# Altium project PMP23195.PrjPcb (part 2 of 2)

## Sheet SystemAUX_ZVSFlyback.SchDoc
size 431 x 279 mm; Date: Not shown in title block; ApprovedBy: Not shown in title block; CheckedBy: Not shown in title block; Author: Not shown in title block; CompanyName: Not shown in title block; Engineer: Not shown in title block; Organization: Not shown in title block; Address1: Not shown in title block; Address2: Not shown in title block; Address3: Not shown in title block; Address4: Not shown in title block; DocumentNumber: 1; Revision: Use project parameter SCH_Rev; SheetNumber: 4; SheetTotal: 4; PageSetup: Record=PageOptions¦CenterHorizontal=True¦CenterVertical=True¦PrintScale=1.00¦XCorrection=1.00¦YCorrection=1.00¦PrintKind=0¦BorderSize=5000000¦LeftOffset=0¦BottomOffset=0¦Orientation=2¦PaperLength=1000¦PaperWidth=1000¦Scale=100¦PaperSource=15¦PrintQuality=600¦MediaType=1¦DitherType=10¦PaperKind=Letter¦PrintScaleMode=1
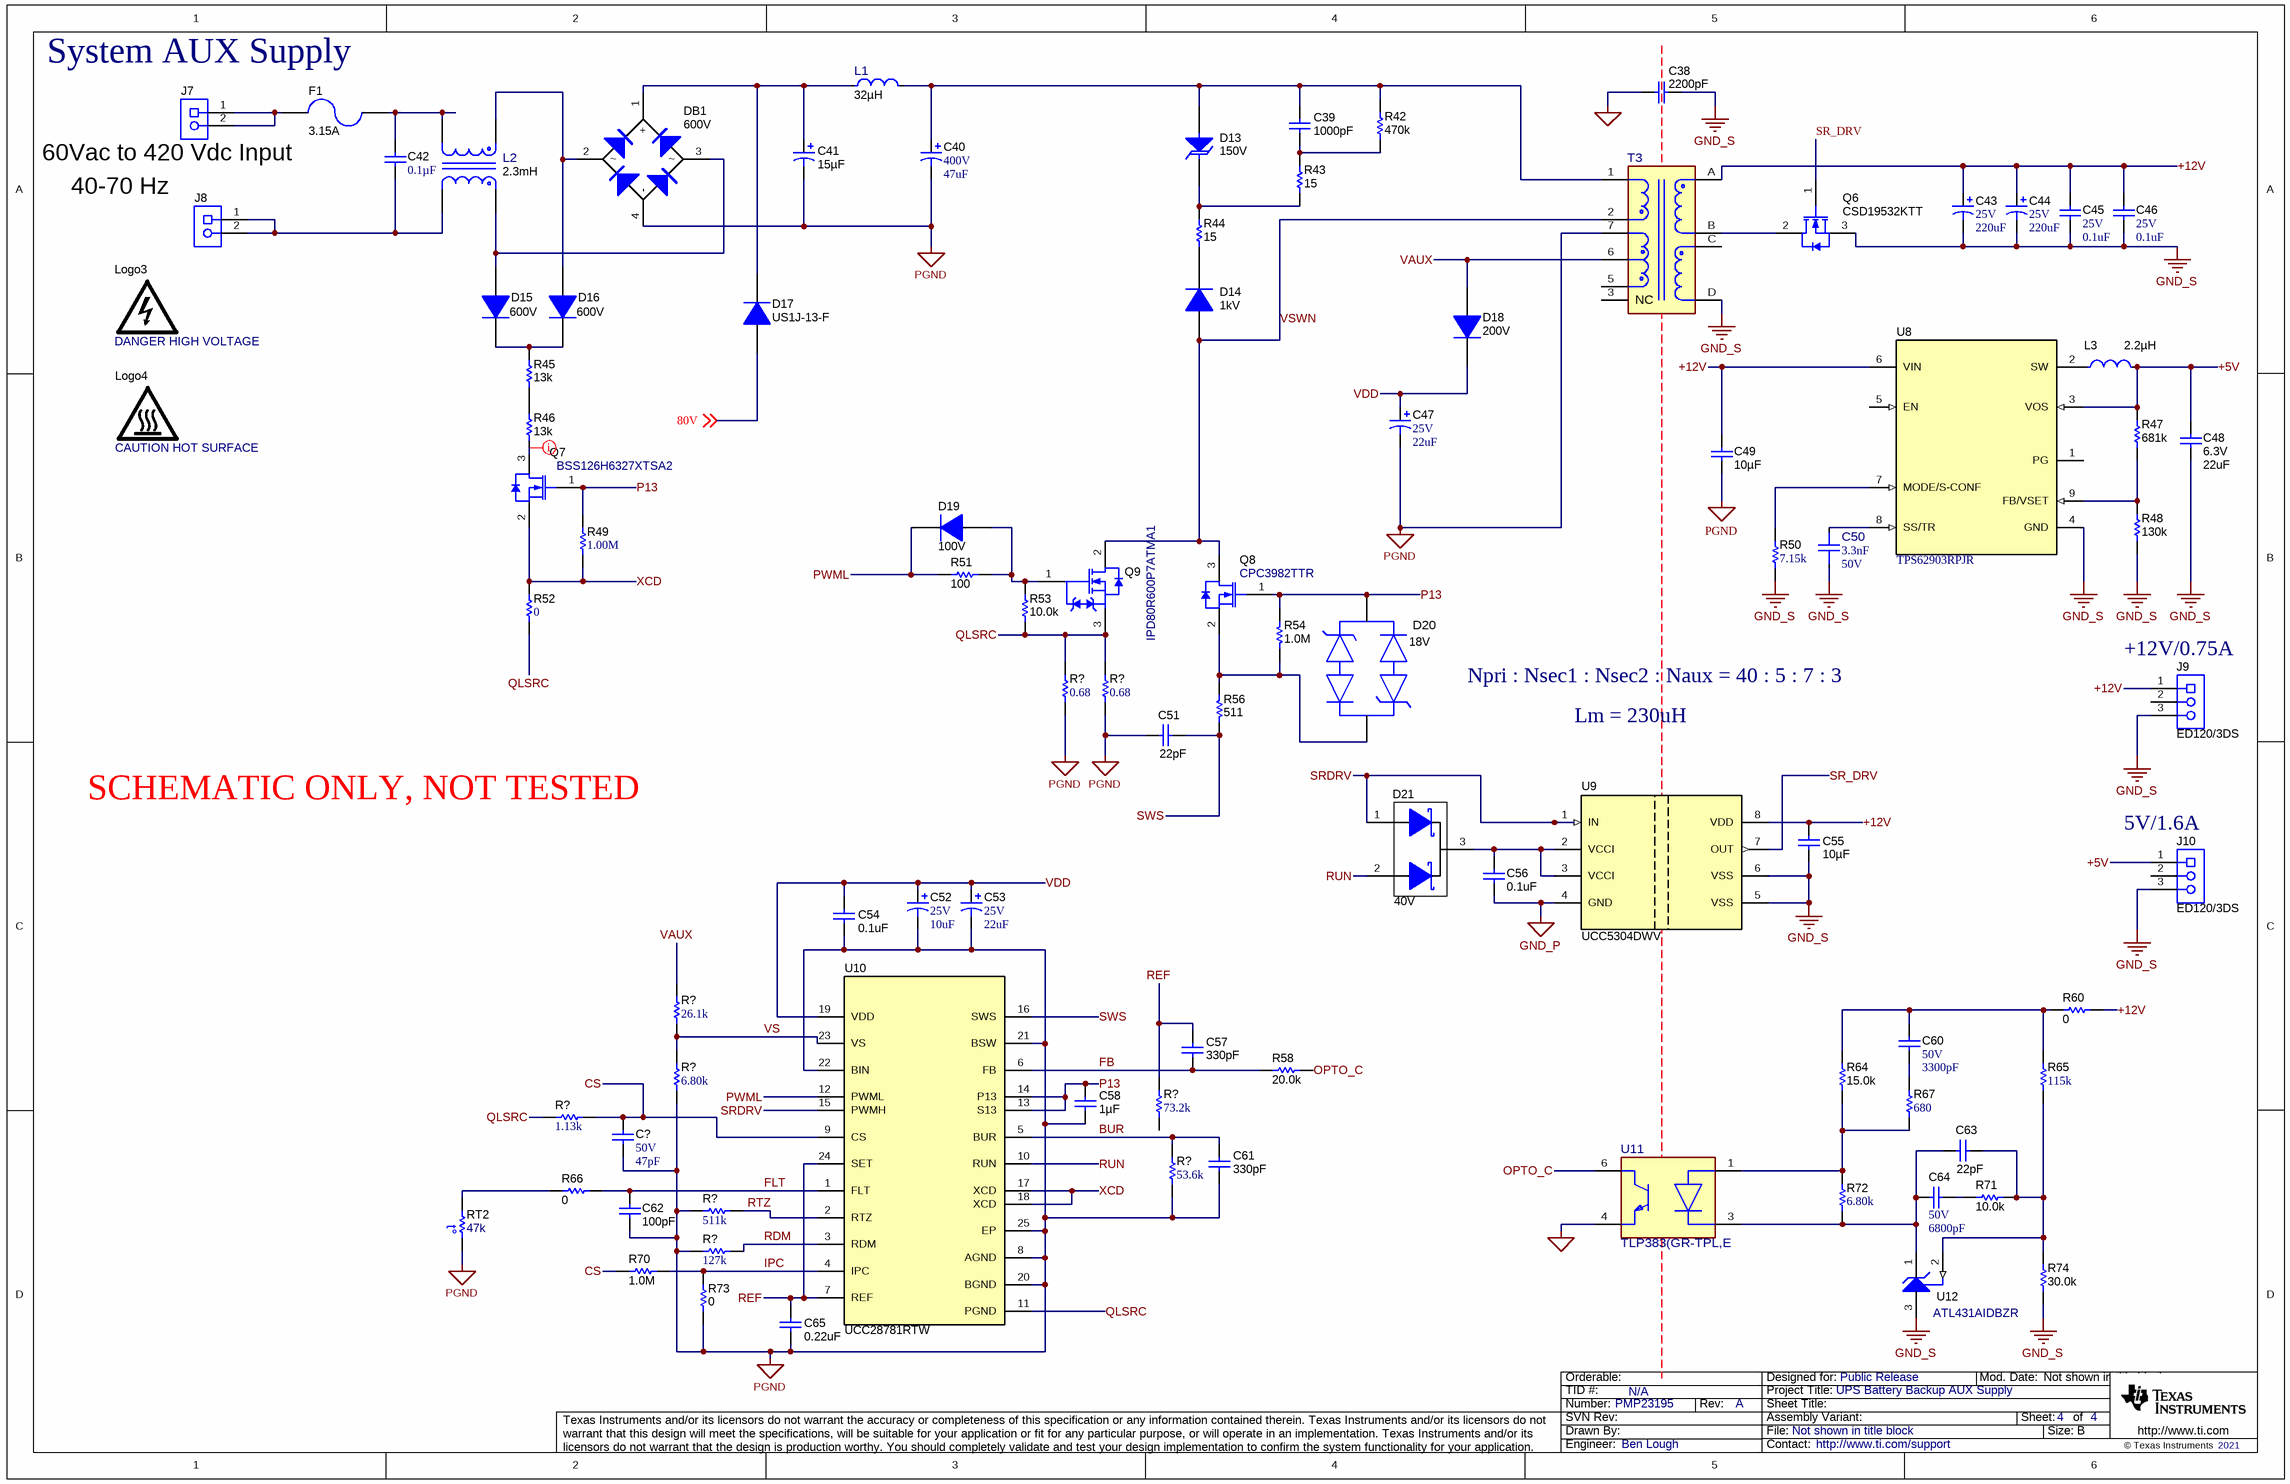
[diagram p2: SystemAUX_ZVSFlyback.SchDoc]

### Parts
(Parts that share a designator on the sheet are numbered #1, #2 ... from top to bottom, then left to right.)
C38  ValueDisplayed: 2200pF  [C900_9x13]  (hidden comment: C921U222MVVDBA7317)
C39  ValueDisplayed: 1000pF  [1206L]  (hidden comment: GRM31BR72J102KW01L)
C40  VDC_V: 400V  ValueDisplayed: 47uF  [CAPPR7.5-16x25]  (hidden comment: UCS2G470MHD)
C41  ValueDisplayed: 15µF  [UVC_1000x1600]  (hidden comment: UVC2G150MPD)
C42  ValueDisplayed: 0.1µF  [B32933_600x1500x2650]  (hidden comment: B32933A3104K000)
C43  VDC_V: 25V  ValueDisplayed: 220uF  [BT_1000x1250]  (hidden comment: UBT1E221MPD1TD)
C44  VDC_V: 25V  ValueDisplayed: 220uF  [BT_1000x1250]  (hidden comment: UBT1E221MPD1TD)
C45  VDC_V: 25V  ValueDisplayed: 0.1uF  [0603]  (hidden comment: 06033D104KAT2A)
C46  VDC_V: 25V  ValueDisplayed: 0.1uF  [0603]  (hidden comment: 06033D104KAT2A)
C47  VDC_V: 25V  ValueDisplayed: 22uF  [SM_RADIAL_D]  (hidden comment: EEE-FC1E220P)
C48  VDC_V: 6.3V  ValueDisplayed: 22uF  [0805_HV]  (hidden comment: CL21A226KQQNNNE)
C49  ValueDisplayed: 10µF  [1206_180]  (hidden comment: GCM31CR71C106KA64L)
C50  ValueDisplayed: 3.3nF  VDC_V: 50V  [FP-885012205064_0402-MFG]  (hidden comment: 885012205064)
C51  ValueDisplayed: 22pF  [0402S]  (hidden comment: GCM1555C1H220JA16D)
C52  VDC_V: 25V  ValueDisplayed: 10uF  [CAPSMT_62_D55]  (hidden comment: EMVA250ADA100MD55G)
C53  VDC_V: 25V  ValueDisplayed: 22uF  [SM_RADIAL_D]  (hidden comment: EEE-FC1E220P)
C54  ValueDisplayed: 0.1uF  [0402S]  (hidden comment: GRM155R71H104ME14D)
C55  ValueDisplayed: 10µF  [1206_180L]  (hidden comment: C1206C106J3RACAUTO)
C56  ValueDisplayed: 0.1uF  [0402S]  (hidden comment: GRM155R71H104ME14D)
C57  ValueDisplayed: 330pF  [0402S]  (hidden comment: GRM155R71H331KA01D)
C58  Cap_F: 1µF  [0603S]  (hidden comment: CGA3E1X7R1V105K080AC)
C60  VDC_V: 50V  ValueDisplayed: 3300pF  [0402]  (hidden comment: GRM155R71H332KA01D)
C61  ValueDisplayed: 330pF  [0402S]  (hidden comment: GRM155R71H331KA01D)
C62  ValueDisplayed: 100pF  [0402S]  (hidden comment: GRM1555C1H101JA01D)
C63  ValueDisplayed: 22pF  [0402S]  (hidden comment: GCM1555C1H220JA16D)
C64  VDC_V: 50V  ValueDisplayed: 6800pF  [0402]  (hidden comment: GRM155R71H682KA88D)
C65  ValueDisplayed: 0.22uF  [0402S]  (hidden comment: GRM155R71C224KA12D)
C?#2  VDC_V: 50V  ValueDisplayed: 47pF  [0402]  (hidden comment: GRM1555C1H470JZ01)
D13  VRWM: 150V  [SMA]  (hidden comment: SMAJ150A)
D14  Vr_V: 1kV  [SMA]  (hidden comment: MRA4007T3G)
D15  Vr_V: 600V  [TUMD2SM]  (hidden comment: RFU02VSM6STR)
D16  Vr_V: 600V  [TUMD2SM]  (hidden comment: RFU02VSM6STR)
D17  US1J-13-F  [SMA]
D18  Vr_V: 200V  [SOD-123H]  (hidden comment: CSFMT104-HF)
D19  Vr_V: 100V  [SOD-323]  (hidden comment: BAS316,115)
D20  CDSOD323-T18C  [FP-CDSOD323-T18C_SOD323-MFG]  (value not drawn)
D21  Vr_V: 40V  [SOT-323]  (hidden comment: BAS40W-05-7-F)
DB1  value 600V  [Z4-D]  (hidden comment: Z4DGP406L-HF)
F1  Irating_A: 3.15A  [FUSE_392]  (hidden comment: 39213150000)
J7  ED120/2DS  [On-Shore_ED120_2DS]  (value not drawn)
J8  ED120/2DS  [On-Shore_ED120_2DS]  (value not drawn)
J9  ED120/3DS  [On-Shore_ED120_3DS]
J10  ED120/3DS  [On-Shore_ED120_3DS]
L1  Ind_H: 32µH  [FP-7447052_PTH_D10MM0-MFG]  (hidden comment: 7447052)
L2  Ind_H: 2.3mH  [FP-RLTI-1387_PTH_CMC_0IN38_0IN60-MFG]  (hidden comment: RLTI-1387)
L3  Ind_H: 2.2µH  [FP-74438336010_SMD2-MFG]  (hidden comment: 74438336022)
Logo3  DANGER HIGH VOLTAGE  [IEC_HighVoltage_Small]  (no BOM)
Logo4  CAUTION HOT SURFACE  [IEC_HotSurface_Small]  (no BOM)
Q6  CSD19532KTT  [KTT0002A]
Q7  BSS126H6327XTSA2  [SOT-23L]
Q8  CPC3982TTR  [SOT-23L]
Q9  IPD80R600P7ATMA1  [DPAK]
R42  ValueDisplayed: 470k  [0805_HV1]  (hidden comment: CRCW0805470KJNEA)
R43  ValueDisplayed: 15  [0805_HV1]  (hidden comment: CRCW080515R0JNEA)
R44  ValueDisplayed: 15  [0805_HV1]  (hidden comment: CRCW080515R0JNEA)
R45  ValueDisplayed: 13k  [1206L]  (hidden comment: CRCW120613K0JNEA)
R46  ValueDisplayed: 13k  [1206L]  (hidden comment: CRCW120613K0JNEA)
R47  ValueDisplayed: 681k  [0402]  (hidden comment: CRCW0402681KFKED)
R48  ValueDisplayed: 130k  [0402]  (hidden comment: CRCW0402130KFKED)
R49  ValueDisplayed: 1.00M  [0603]  (hidden comment: MCT06030C1004FP500)
R50  ValueDisplayed: 7.15k  [0402]  (hidden comment: CRCW04027K15FKED)
R51  ValueDisplayed: 100  [0805_HV1]  (hidden comment: CRCW0805100RJNEA)
R52  ValueDisplayed: 0  [0603]  (hidden comment: RC0603JR-070RL)
R53  ValueDisplayed: 10.0k  [0402S]  (hidden comment: CRCW040210K0FKED)
R54  ValueDisplayed: 1.0M  [0402S]  (hidden comment: CRCW04021M00JNED)
R56  ValueDisplayed: 511  [0402S]  (hidden comment: CRCW0402511RFKED)
R58  ValueDisplayed: 20.0k  [0402S]  (hidden comment: CRCW040220K0FKED)
R60  ValueDisplayed: 0  [0402S]  (hidden comment: RC0402JR-070RL)
R64  ValueDisplayed: 15.0k  [0402S]  (hidden comment: CRCW040215K0FKED)
R65  ValueDisplayed: 115k  [0402]  (hidden comment: RC1005F1153CS)
R66  ValueDisplayed: 0  [0402S]  (hidden comment: CRCW04020000Z0EDHP)
R67  ValueDisplayed: 680  [0603]  (hidden comment: RC0603FR-07680RL)
R70  ValueDisplayed: 1.0M  [0402S]  (hidden comment: CRCW04021M00JNED)
R71  ValueDisplayed: 10.0k  [0402S]  (hidden comment: CRCW040210K0FKED)
R72  ValueDisplayed: 6.80k  [0603]  (hidden comment: RC0603FR-076K8L)
R73  ValueDisplayed: 0  [0402S]  (hidden comment: CRCW04020000Z0EDHP)
R74  ValueDisplayed: 30.0k  [0402S]  (hidden comment: CRCW040230K0FKED)
R?#10  ValueDisplayed: 0.68  [1206]  (hidden comment: ERJ-8RQFR68V)
R?#11  ValueDisplayed: 0.68  [1206]  (hidden comment: ERJ-8RQFR68V)
R?#12  ValueDisplayed: 26.1k  [0603]  (hidden comment: RC0603FR-0726K1L)
R?#13  ValueDisplayed: 6.80k  [0402]  (hidden comment: RC0402FR-076K8L)
R?#14  ValueDisplayed: 73.2k  [0402]  (hidden comment: CRCW040273K2FKED)
R?#15  ValueDisplayed: 1.13k  [0402]  (hidden comment: CRCW04021K13FKED)
R?#16  ValueDisplayed: 53.6k  [0402]  (hidden comment: CRCW040253K6FKED)
R?#17  ValueDisplayed: 511k  [0402]  (hidden comment: CRCW0402511KFKED)
R?#18  ValueDisplayed: 127k  [0402]  (hidden comment: CRCW0402127KFKED)
RT2  value 47k  [0603S]  (hidden comment: NCP18WB473J03RB)
T3  RLTI-1324  [FP-RLTI-1324_PTH_0IN980_0IN766-MFG]  (value not drawn)
U8  TPS62903RPJR  [RPJ0009A]
U9  UCC5304DWV  [DWV0008A]
U10  UCC28781RTW  [RTW0024B]
U11  TLP383(GR-TPL,E  [FP-TLP383(GR-TPL,E_SO6-4-MFG]
U12  ATL431AIDBZR  [DBZ0003A_L]

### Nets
GND2: C38.2 U11.4(Emitter)
GND_P: C56.2 U9.4(GND)
GND_S: C38.1 C43.2(-) C44.2(-) C45.2 C46.2 C48.2 C50.1 C55.2 J9.3 J10.3 Q6.3(S) R48.1 R50.1 R74.2 T3.D U8.4(GND) U9.5(VSS) U9.6(VSS) U12.3(ANODE)
PGND: C40.2(-) C41.2(-) C47.2(-) C49.2 C51.1 C52.2(-) C53.2(-) C54.2 C58.2 C61.2 C62.1 C65.2 C?#2.2 DB1.4(-) R73.1 R?#10.1 R?#11.1 R?#13.1 R?#16.1 R?#17.1 R?#18.1 RT2.2 T3.7 U10.8(AGND) U10.20(BGND) U10.21(BSW) U10.22(BIN) U10.25(EP)
80V: D17.2(A) ; off-sheet 80V
+5V: C48.1 J10.1 L3.2 R47.2 U8.3(VOS)
+12V: C43.1(+) C44.1(+) C45.1 C46.1 C49.1 C55.1 J9.1 R60.1 T3.A U8.6(VIN) U9.8(VDD)
BUR: C61.1 R?#16.2 U10.5(BUR)
CS: C?#2.1 R70.2 R?#15.2 U10.9(CS)
FB: C57.2 R58.1 U10.6(FB)
FLT: C62.2 R66.2 U10.1(FLT)
IPC: R70.1 R73.2 U10.4(IPC)
OPTO_C: R58.2 U11.6(Collector)
P13: C58.1 D20.2 Q7.1(G) Q8.1(G) R49.2 R54.2 U10.13(S13) U10.14(P13)
PWML: D19.1(K) R51.1 U10.12(PWML)
QLSRC: Q9.3(S) R52.1 R53.1 R?#10.2 R?#11.2 R?#15.1 U10.11(PGND)
RDM: R?#18.2 U10.3(RDM)
REF: C57.1 C65.1 R?#14.2 U10.7(REF) U10.24(SET)
RTZ: R?#17.2 U10.2(RTZ)
RUN: D21.2(A) U10.10(RUN)
SR_DRV: Q6.1(G) U9.7(OUT)
SRDRV: D21.1(A) U9.1(IN) U10.15(PWMH)
SWS: C51.2 R56.1 U10.16(SWS)
VAUX: D18.2(A) R?#12.2 T3.6
VDD: C47.1(+) C52.1(+) C53.1(+) C54.1 D18.1(K) U10.19(VDD)
VS: R?#12.1 R?#13.2 U10.23(VS)
VSWN: D14.2(A) Q8.3(D) Q9.2(D) T3.2
XCD: Q7.2(S) R49.1 R52.2 U10.17(XCD) U10.18(XCD)
NetC39_1: C39.1 C40.1(+) D13.2(A) L1.2 R42.2 T3.1
NetC39_2: C39.2 R42.1 R43.2
NetC41_1: C41.1(+) D17.1(K) DB1.1(+) L1.1
NetC42_1: C42.1 F1.1 L2.3
NetC42_2: C42.2 J8.1 J8.2 L2.2
NetC50_2: C50.2 U8.8(SS/TR)
NetC56_1: C56.1 D21.3(K) U9.2(VCCI) U9.3(VCCI)
NetC60_1: C60.1 R60.2 R64.2 R65.2
NetC60_2: C60.2 R67.2
NetC63_1: C63.1 C64.2 R72.1 U11.3(Cathode) U12.1(CATHODE)
NetC63_2: C63.2 R65.1 R71.2 R74.1 U12.2(REF)
NetC64_1: C64.1 R71.1
NetD13_1: D13.1(K) R43.1 R44.2
NetD14_1: D14.1(K) R44.1
NetD15_1: D15.1(K) D16.1(K) R45.1
NetD15_2: D15.2(A) DB1.3 L2.1
NetD16_2: D16.2(A) DB1.2 L2.4
NetD19_2: D19.2(A) Q9.1(G) R51.2 R53.2
NetD20_1: D20.1 Q8.2(S) R54.1 R56.2
NetF1_2: F1.2 J7.1 J7.2
NetL3_1: L3.1 U8.2(SW)
NetQ6_2: Q6.2(D) T3.B
NetQ7_3: Q7.3(D) R46.2
NetR45_2: R45.2 R46.1
NetR47_1: R47.1 R48.2 U8.9(FB/VSET)
NetR50_2: R50.2 U8.7(MODE/S-CONF)
NetR64_1: R64.1 R67.1 R72.2 U11.1(Anode)
NetR66_1: R66.1 RT2.1

Not connected (* = marked no-connect by the designer): J9 2; J10 2; R?#14 1; T3 3(NC) 5 C; U8 1(PG) 5(EN)

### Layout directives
net class HV: NetQ7_3

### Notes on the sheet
- System AUX Supply
- (near J7) 60Vac to 420 Vdc Input
- 40-70 Hz
- (near D20) 18V
- Npri : Nsec1 : Nsec2 : Naux = 40 : 5 : 7 : 3
- (near J9) +12V/0.75A
- Lm = 230uH
- SCHEMATIC ONLY, NOT TESTED
- (near J10) 5V/1.6A

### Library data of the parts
C38 = CMP-0078358-1: CAP, CERM, 2200 pF, X1 400 VAC/Y1 400 VAC, +/- 20%, Y5V, D9xL13mm; Manufacturer: Kemet; Cap_F: 2.2nF; SizeAreaWB_mm2: 121; VAC_X: 400V; SizeArea_mm2: 81; AEC Qualified: N; AEC Category: Q200; Value: 2200pF; TaMax_C: 125°C; SizeZ_mm: 13; TaMin_C: -40°C; SizeY_mm: 9; U/M: EA; AC_Safety: X1Y1; Cap_Case: 9x13mm
C39 = CMP-0008909-2: CAP, CERM, 1000 pF, 630 V, +/- 10%, X7R, 1206; Manufacturer: MuRata; TaMin_C: -55°C; Polarized: N; SizeAreaWB_mm2: 10.92; Value1: Unknown; U/M: EA; Value: 1000pF; TaMax_C: 125°C; SizeZ_mm: 1.35; SizeX_mm: 3.2; SizeY_mm: 1.6; Cap_Case: 1206; Value2: 630V; SizeArea_mm2: 5.12; Cap_F: 1nF; AEC Category: Q200
C40 = CMP-0010241-2: CAP, AL, 47 uF, 400 V, +/- 20%, TH; Manufacturer: Nichicon; TaMin_C: -40°C; Polarized: Y; SizeAreaWB_mm2: 324; Value1: Unknown; U/M: EA; Value: 47uF; TaMax_C: 105°C; SizeZ_mm: 25; SizeX_mm: 16; Cap_Case: Radial  16x25mm; SizeArea_mm2: 256; CompType: Capacitor; AEC Qualified: N; Cap_F: 47µF; IRMS_A: 1.18A; AEC Category: Q200
C41 = CMP-0860955-2: CAP, AL, 15 µF, 400 V, +/- 20%, AEC-Q200 Grade 2, TH; Manufacturer: Nichicon; SizeArea_mm2: 100; CompType: Capacitor; Value2: 400V; SizeZ_mm: 18; IRMS_A: 180mA; Polarized: Y; SizeX_mm: 10; Value: 15uF; TaMin_C: -40°C; AEC Grade: 2; U/M: EA; SizeAreaWB_mm2: 144; Cap_Case: 10x16; TaMax_C: 105°C; AEC Category: Q200
C42 = CMP-0077664-2: CAP, Film, 0.1 µF, X2 305 VAC, +/- 10%, AEC-Q200 Grade 2, TH; Manufacturer: TDK; TaMin_C: -40°C; Polarized: N; SizeAreaWB_mm2: 210.0; Value: 0.1uF; TaMax_C: 105°C; VAC_X: 305; SizeZ_mm: 15.0; SizeX_mm: 26.0; SizeY_mm: 5.5; SizeArea_mm2: 143.0; AEC Qualified: Y; Cap_F: 100nF; AEC Grade: 2; AEC Category: Q200
C43 C44 = CMP-0010527-1: CAP, AL, 220 uF, 25 V, +/- 20%, 0.1 ohm, TH; Manufacturer: Nichicon; TaMin_C: -40°C; ESR_ohm: 1d; Polarized: Y; SizeAreaWB_mm2: 144; Value1: 0.1 ohm; U/M: EA; Value: 220uF; TaMax_C: 125°C; SizeZ_mm: 14.5; SizeX_mm: 10; Cap_Case: 10x12.5mm; SizeArea_mm2: 100; CompType: Capacitor; Cap_F: 220µF; IRMS_A: 6.8dA; AEC Category: Q200
C45 C46 = CMP-0006758-5: CAP, CERM, 0.1 uF, 25 V, +/- 10%, X5R, 0603; Manufacturer: AVX; TaMin_C: -55°C; ESR_ohm: 0.048; Polarized: N; SizeAreaWB_mm2: 4.68; Value1: 0.048 ohm; U/M: EA; Value: 0.1uF; TaMax_C: 85°C; SizeZ_mm: 1; SizeX_mm: 1.6; SizeY_mm: 0.8; SizeArea_mm2: 1.28; Cap_F: 100nF; IRMS_A: 5.3dA; AEC Category: Q200
C47 C53 = CMP-0010654-1: CAP, AL, 22 uF, 25 V, +/- 20%, 1 ohm, SMD; Manufacturer: Panasonic; TaMin_C: -40°C; ESR_ohm: 1; Polarized: Y; SizeAreaWB_mm2: 84.28; Value1: 1 ohm; U/M: EA; Value: 22uF; TaMax_C: 105°C; SizeZ_mm: 5.4; SizeX_mm: 7.8; SizeY_mm: 6.6; Cap_Case: D; SizeArea_mm2: 51.48; CompType: Capacitor; Cap_F: 22µF; IRMS_A: 1.15dA; AEC Category: Q200
C48 = CMP-0007989-2: CAP, CERM, 22 uF, 6.3 V, +/- 10%, X5R, 0805; Manufacturer: Samsung Electro-Mechanics; TaMin_C: -55°C; Polarized: N; SizeAreaWB_mm2: 6.75; Value1: Unknown; U/M: EA; Value: 22uF; TaMax_C: 85°C; SizeZ_mm: 1.45; SizeX_mm: 2; SizeY_mm: 1.25; Cap_Case: 0805; SizeArea_mm2: 2.5; CompType: Capacitor; Cap_F: 22µF; AEC Category: Q200
C49 = GCM31CR71C106KA64L: CAP, CERM, 10 µF, 16 V,+/- 10%, X7R, AEC-Q200 Grade 1, 1206; Manufacturer: MuRata; Polarized: N; CompType: Capacitor; Value: 10uF; U/M: EA; Cap_F: 0.00001; Tolerance_%: 10; VDC_V: 16; Value2: 16V; TaMin_C: -55; TaMax_C: 125; Cap_Case: 1206; SizeArea_mm2: 5.12; SizeAreaWB_mm2: 10.92; SizeX_mm: 3.2; SizeY_mm: 1.6; SizeZ_mm: 1.8; AEC Category: Q200; AEC Qualified: Y; AEC Grade: 1; Green_Lifecycle: Active; Green_REACh: Passed
C50 = CMP-0092424-1: Cap Cer 3300pF 50V X7R 0402; Manufacturer: Wurth Electronics; TempCo: 15%; AEC Qualified: No; Value: 3.3nF; SizeZ_mm: 0.55mm; Tolerance_%: 10%
C51 C63 = CMP-0006348-2: CAP, CERM, 22 pF, 50 V, +/- 5%, C0G/NP0, AEC-Q200 Grade 1, 0402; Manufacturer: MuRata; TaMin_C: -55°C; Polarized: N; SizeAreaWB_mm2: 3; Value1: Unknown; U/M: EA; Value: 22pF; TaMax_C: 125°C; SizeZ_mm: 0.6; SizeX_mm: 1; SizeY_mm: 0.5; Cap_Case: 0402; Value2: 50V; AEC Qualified: Y; AEC Category: Q200
C52 = CMP-0010785-1: CAP, AL, 10 uF, 25 V, +/- 20%, SMD; Manufacturer: Chemi-Con; TaMin_C: -40°C; Polarized: Y; SizeAreaWB_mm2: 28.09; Value1: Unknown; U/M: EA; Value: 10uF; TaMax_C: 85°C; SizeZ_mm: 5.2; SizeX_mm: 4.3; Cap_Case: D55; SizeArea_mm2: 18.49; CompType: Capacitor; Cap_F: 10µF; IRMS_A: 24mA; AEC Category: Q200
C54 C56 = CMP-0006675-2: CAP, CERM, 0.1 uF, 50 V, +/- 20%, X7R, 0402; Manufacturer: MuRata; TaMin_C: -55°C; Polarized: N; SizeAreaWB_mm2: 3; Value1: Unknown; U/M: EA; Value: 0.1uF; TaMax_C: 125°C; SizeZ_mm: 0.6; SizeX_mm: 1; SizeY_mm: 0.5; Cap_Case: 0402; Value2: 50V; Cap_F: 100nF; AEC Category: Q200
C55 = CMP-0081062-1: CAP, CERM, 10 µF, 25 V,+/- 5%, X7R, AEC-Q200 Grade 1, 1206; Manufacturer: Kemet; TaMin_C: -55°C; Polarized: N; SizeAreaWB_mm2: 10.92; U/M: EA; Value: 10uF; TaMax_C: 125°C; SizeZ_mm: 1.8; SizeX_mm: 3.2; SizeY_mm: 1.6; Cap_Case: 1206_180; Value2: 25V; SizeArea_mm2: 5.12; AEC Qualified: Y; AEC Grade: 1; AEC Category: Q200
C57 C61 = CMP-0006687-2: CAP, CERM, 330 pF, 50 V, +/- 10%, X7R, 0402; Manufacturer: MuRata; TaMin_C: -55°C; Polarized: N; SizeAreaWB_mm2: 3; Value1: Unknown; U/M: EA; Value: 330pF; TaMax_C: 125°C; SizeZ_mm: 0.6; SizeX_mm: 1; SizeY_mm: 0.5; Cap_Case: 0402; Value2: 50V; AEC Category: Q200
C58 = CMP-0007067-4: CAP, CERM, 1 uF, 35 V, +/- 10%, X7R, AEC-Q200 Grade 1, 0603; Manufacturer: TDK; TaMin_C: -55°C; ESR_ohm: 5.522m; Polarized: N; SizeAreaWB_mm2: 4.68; Value1: 0.005522 ohm; U/M: EA; Value: 1uF; TaMax_C: 125°C; SizeZ_mm: 1; SizeX_mm: 1.6; SizeY_mm: 0.8; Cap_Case: 0603; Value2: 35V; SizeArea_mm2: 1.28; AEC Qualified: Y; IRMS_A: 2.21617A; AEC Category: Q200
C60 = CMP-0006688-2: CAP, CERM, 3300 pF, 50 V, +/- 10%, X7R, 0402; Manufacturer: MuRata; TaMin_C: -55°C; Polarized: N; SizeAreaWB_mm2: 3; Value1: Unknown; U/M: EA; Value: 3300pF; TaMax_C: 125°C; SizeZ_mm: 0.6; SizeX_mm: 1; SizeY_mm: 0.5; Cap_F: 3.3nF; AEC Category: Q200
C62 = CMP-0006410-2: CAP, CERM, 100 pF, 50 V, +/- 5%, C0G/NP0, 0402; Manufacturer: MuRata; TaMin_C: -55°C; Polarized: N; SizeAreaWB_mm2: 3; Value1: Unknown; U/M: EA; Value: 100pF; TaMax_C: 125°C; SizeZ_mm: 0.6; SizeX_mm: 1; SizeY_mm: 0.5; Cap_Case: 0402; Value2: 50V; AEC Category: Q200
C64 = CMP-0006696-2: CAP, CERM, 6800 pF, 50 V, +/- 10%, X7R, 0402; Manufacturer: MuRata; TaMin_C: -55°C; Polarized: N; SizeAreaWB_mm2: 3; Value1: Unknown; U/M: EA; Value: 6800pF; TaMax_C: 125°C; SizeZ_mm: 0.6; SizeX_mm: 1; SizeY_mm: 0.5; Cap_F: 6.8nF; AEC Category: Q200
C65 = CMP-0006648-2: CAP, CERM, 0.22 uF, 16 V, +/- 10%, X7R, 0402; Manufacturer: MuRata; TaMin_C: -55°C; Polarized: N; SizeAreaWB_mm2: 3; Value1: Unknown; U/M: EA; Value: 0.22uF; TaMax_C: 125°C; SizeZ_mm: 0.6; SizeX_mm: 1; SizeY_mm: 0.5; Cap_Case: 0402; Value2: 16V; Cap_F: 220nF; AEC Category: Q200
C?#2 = CMP-0006469-2: CAP, CERM, 47 pF, 50 V, +/- 5%, C0G/NP0, 0402; Manufacturer: MuRata; TaMin_C: -55°C; ESR_ohm: 0.045; Polarized: N; SizeAreaWB_mm2: 3; Value1: 0.045 ohm; U/M: EA; Value: 47pF; TaMax_C: 125°C; SizeZ_mm: 0.6; SizeX_mm: 1; SizeY_mm: 0.5; AEC Category: Q200
D13 = CMP-0084982-1: Diode, TVS, Uni, 150 V, 243 Vc, 400 W, 1.6 A, SMA; Manufacturer: Littelfuse; Vc: 243V; Ipp: 1.6A; RJA_CperW: 120; AEC Qualified: N; Value: 150V; Ppk: 400W; AEC Category: Q101; SizeArea_mm2: 16.3228; SizeAreaWB_mm2: 37.3428; SizeZ_mm: 2.87; Vbr_Max: 185V; SizeX_mm: 5.59; SizeY_mm: 2.92; Vbr_Min: 167V
D14 = CMP-0077082-2: Diode, Standard Recovery Rectifier, 1000 V, 1 A, AEC-Q101, SMA; Manufacturer: ON Semiconductor; SizeAreaWB_mm2: 37.3428; SizeArea_mm2: 16.3228; AEC Qualified: Y; TJmax_C: 175°C; AEC Category: Q101; Value: 1000V; SizeZ_mm: 2.87; Green_REACh: Passed; Io_A: 1A; Vf_V: 1.1V; SizeY_mm: 2.92; Green_Lifecycle: Active; SizeX_mm: 5.59; RJC_CperW: 16.2
D15 D16 = CMP-0080762-2: Diode, Standard Recovery Rectifier, 600 V, 0.2 A, 2x1.4mm; Manufacturer: Rohm; SizeArea_mm2: 3.5; AEC Qualified: N; SizeY_mm: 1.4; Io_A: 200mA; SizeZ_mm: 0.8; Vf_V: 2.2V; SizeAreaWB_mm2: 8.4; TJmax_C: 150°C; Value1: 0.2A; SizeX_mm: 2.5; AEC Category: Q101; Value: 600V
D17 = CMP-0077027-2: Diode, Ultrafast, 600 V, 1 A, SMA; Manufacturer: Diodes Inc.; Value: 600V; TJmax_C: 150°C; Value1: 1A; Value2: 1.7V; SizeY_mm: 2.92; Green_REACh: Passed; Green_Lifecycle: Active; SizeX_mm: 5.59; AEC Category: Q101; SizeAreaWB_mm2: 37.3428; SizeZ_mm: 2.87; SizeArea_mm2: 16.3228
D18 = CMP-0029199-2: Diode, Superfast Rectifier, 200 V, 1 A, 3.5x1.6mm; Manufacturer: Comchip Technology; Vf_V: 950mV; Value: 200V; Value1: 1A; Value2: 0.95V; TJmax_C: 150°C; SizeAreaWB_mm2: 11.7; SizeArea_mm2: 5.6; SizeX_mm: 3.5; SizeY_mm: 1.6; SizeZ_mm: 1; AEC Category: Q101; AEC Qualified: N
D19 = CMP-0029006-2: Diode, Ultrafast, 100 V, 0.25 A, SOD-323; Manufacturer: Nexperia; SizeY_mm: 1.35; Value1: 0.25A; SizeAreaWB_mm2: 8.695; SizeZ_mm: 1; Io_A: 250mA; Value2: 1.4V; SizeX_mm: 2.7; Green_REACh: Incomplete; TJmax_C: 150°C; Green_Lifecycle: Not Set; AEC Category: Q101; Value: 100V; SizeArea_mm2: 3.645
D20 = CMP-0087587-1: Diode, TVS, Bi, 18 V, SOD-323; Manufacturer: Bourns Inc.; SizeZ_mm: 1.14mm; AEC Qualified: No
D21 = CMP-0028437-2: Diode, Schottky, 40 V, 0.2 A, SOT-323; Manufacturer: Diodes Inc.; Io_A: 200mA; Green_Lifecycle: Not Set; SizeAreaWB_mm2: 10.24; Green_REACh: Incomplete; Value1: 0.2A; Value: 40V; SizeZ_mm: 1.1; SizeX_mm: 2.2; Vf_V: 800mV; Value2: 0.8V; SizeArea_mm2: 4.84; AEC Category: Q101
DB1 = Z4DGP406L-HF: Diode, P-N-Bridge, 600 V, 4 A, Z4-D; Manufacturer: Comchip Technology; U/M: EA; Vf_V: 0.95; Value1: 4A; Value2: 0.95V; Io_A: 4; Vr_V: 600; TJmax_C: 175; SizeAreaWB_mm2: 126.25; SizeArea_mm2: 85.05; SizeX_mm: 10.5; SizeY_mm: 8.1; SizeZ_mm: 1.55; AEC Category: Q101; AEC Qualified: N; Green_Lifecycle: Not Set; Green_REACh: Incomplete
F1 = CMP-0003561-2: Fuse, 3.15 A, 250VAC/VDC, TH; Manufacturer: Littelfuse; VAC_V: 250V
J7 J8 = CMP-0074910-1: Terminal Block, 5.08 mm, 2x1, Brass, TH; Manufacturer: On-Shore Technology; Pitch_mm: 5.08; Gender: Female; Shrouded: N; Row_Count: 1; Current_A: 15A; Voltage_V: 300V; Cert_CULUS: Y; CNHeader: False; CT: True; Green_Lifecycle: Not Set; Green_REACh: Incomplete
J9 J10 = CMP-0074911-1: Terminal Block, 5.08 mm, 3x1, Brass, TH; Manufacturer: On-Shore Technology; Cert_VDE: Y; CNHeader: False; Current_A: 15A; Green_Lifecycle: Not Set; Shrouded: N; Gender: Female; Green_REACh: Incomplete; Voltage_V: 300V; Row_Count: 1; Pitch_mm: 5.08; CT: True
L1 = CMP-0087546-1: WE-FI Leaded Toroidal Line Choke; Manufacturer: Wurth; SizeZ_mm: 10mm; Irms: 2.6A; DCR_ohm: 0.045; AEC Qualified: No; Symbol Name: SYM-7447052
L2 = CMP-0092946-1: Common Mode Choke, 2.3mH 35%, 0.6x0.38x0.75 IN; Manufacturer: Renco; Test Frequency: 10kHz; SizeZ_mm: 0.75inch; DCR_ohm: 0.03; AEC Qualified: No
L3 = CMP-0087867-1: 2.2µH Shielded Molded Inductor 2.4A 67mOhm Max 2-SMD; Manufacturer: Wurth Electronics; SizeZ_mm: 2mm; Material: Metal Composite; Isat: 4.3A; Symbol Name: SYM-74438336010; DCR_ohm: 0.032; AEC Grade: Grade 1; AEC Qualified: Yes
Logo3 = CMP-0074835-1: IEC 61010-1 High Voltage Warning; SymbolCreator: a0412235
Logo4 = CMP-0074837-1: IEC 61010-1 Hot Surface Warning; SymbolCreator: a0412235
Q6 = CMP-0000957-3: MOSFET, N-CH, 100 V, 136 A, KTT0002A (TO-263-2); Alternate Manufacturer: None; Manufacturer: Texas Instruments; SizeZ_mm: 4.7; ChType: N; Value2: 44 nC; VdsMax_V: 100V; SizeX_mm: 14.3; SizeAreaWB_mm2: 198.208; SizeY_mm: 10.16; Vgs_V: 20V; QgTyp_nC: 44; Value: 100V; SizeArea_mm2: 145.288; AEC Category: Q101; IdsMax_A: 136A
Q7 = CMP-0067574-2: MOSFET, N-CH, Depletion Mode, 100 V, 0.17 A, AEC-Q101, SOT-23; Manufacturer: Infineon Technologies; Alternate Manufacturer: None; ChType: N; Value: 600V; Value1: ? ohm; Value2: 1.4 nC; QgTyp_nC: 1.4; Vgs_V: 20V; IdsMax_A: 21mA; SizeAreaWB_mm2: 14.0; SizeArea_mm2: 7.5; SizeX_mm: 2.5; SizeY_mm: 3.0; SizeZ_mm: 1.1; AEC Category: Q101; AEC Qualified: Y
Q8 = CMP-0081263-2: MOSFET, N-CH, Depletion Mode, 800 V, SOT-23; Alternate Manufacturer: None; Manufacturer: IXYS; SizeAreaWB_mm2: 14; Vgs_V: 15V; Value1: ? ohm; VdsMax_V: 800V; Value: 800V; SizeZ_mm: 1.1; SizeX_mm: 2.5; SizeY_mm: 3; Value2: ? nC; SizeArea_mm2: 7.5; ChType: N; AEC Category: Q101
Q9 = CMP-0083711-2: MOSFET, N-CH, 800 V, 8 A, DPAK; Manufacturer: Infineon Technologies; Alternate Manufacturer: None; AEC Qualified: N; Vgs_V: 20V; SizeY_mm: 6.54; VdsMax_V: 800V; IdsMax_A: 8A; SizeX_mm: 9.91; Value2: 20 nC; AEC Category: Q101; ChMode: Enhancement; SizeAreaWB_mm2: 101.7114; Value1: ? ohm; SizeArea_mm2: 64.8114; Value: 800V; SizeZ_mm: 2.29; QgTyp_nC: 20
R42 = CMP-0020554-3: RES, 470 k, 5%, 0.125 W, AEC-Q200 Grade 0, 0805; Manufacturer: Vishay-Dale; Power_W: 125mW; TempCo: 200 ppm/C; Value: 470k; EIA_Code: E24; SizeX_mm: 2; SizeY_mm: 1.25; SizeZ_mm: 1.45; Value2: 0.125W; SizeArea_mm2: 2.5; AEC Qualified: Y; VDC_V: 150V; AEC Category: Q200; AEC Grade: 0
R43 R44 = CMP-0020464-3: RES, 15, 5%, 0.125 W, AEC-Q200 Grade 0, 0805; Manufacturer: Vishay-Dale; Power_W: 125mW; TempCo: 200 ppm/C; Value_Code: 15R0; Value: 15; EIA_Code: E24; SizeX_mm: 2; SizeY_mm: 1.25; SizeZ_mm: 1.45; Value2: 0.125W; SizeArea_mm2: 2.5; AEC Qualified: Y; VDC_V: 150V; AEC Category: Q200; AEC Grade: 0
R45 R46 = CMP-0018589-3: RES, 13 k, 5%, 0.25 W, AEC-Q200 Grade 0, 1206; Manufacturer: Vishay-Dale; Power_W: 250mW; TempCo: 200 ppm/C; Value_Code: 13k0; Value: 13k; EIA_Code: E24; SizeX_mm: 3.2; SizeY_mm: 1.6; SizeZ_mm: 1.35; Value2: 0.25W; SizeArea_mm2: 5.12; AEC Qualified: Y; VDC_V: 200V; AEC Category: Q200; AEC Grade: 0
R47 = CMP-0026504-2: RES, 681 k, 1%, 0.063 W, AEC-Q200 Grade 0, 0402; Manufacturer: Vishay-Dale; Power_W: 63mW; TempCo: 100 ppm/C; Value: 681k; EIA_Code: E96; SizeX_mm: 1; SizeY_mm: 0.5; SizeZ_mm: 0.6; Value2: 0.063W; CompType: Resistor; AEC Qualified: Y; VDC_V: 50V; AEC Category: Q200; AEC Grade: 0
R48 = CMP-0025997-3: RES, 130 k, 1%, 0.063 W, AEC-Q200 Grade 0, 0402; Manufacturer: Vishay-Dale; Power_W: 63mW; TempCo: 100 ppm/C; Value: 130k; EIA_Code: E96; SizeX_mm: 1; SizeY_mm: 0.5; SizeZ_mm: 0.6; Value2: 0.063W; CompType: Resistor; AEC Qualified: Y; VDC_V: 50V; AEC Category: Q200; AEC Grade: 0
R49 = CMP-0022731-2: RES, 1.00 M, 1%, 0.125 W, 0603; Manufacturer: Vishay/Beyschlag; Power_W: 125mW; TempCo: 50 ppm/C; Value_Code: 1M00; U/M: EA; Value: 1.00Meg; EIA_Code: E96; Res_ohm: 1M; SizeX_mm: 1.6; SizeY_mm: 0.8; SizeZ_mm: 1; Value2: 0.125W; SizeArea_mm2: 1.28; AEC Qualified: N; VDC_V: 75V; AEC Category: Q200
R50 = CMP-0026553-2: RES, 7.15 k, 1%, 0.063 W, AEC-Q200 Grade 0, 0402; Manufacturer: Vishay-Dale; Power_W: 63mW; TempCo: 100 ppm/C; Value_Code: 7k15; Value: 7.15k; EIA_Code: E96; SizeX_mm: 1; SizeY_mm: 0.5; SizeZ_mm: 0.6; Value2: 0.063W; AEC Qualified: Y; VDC_V: 50V; AEC Category: Q200; AEC Grade: 0
R51 = CMP-0020445-3: RES, 100, 5%, 0.125 W, AEC-Q200 Grade 0, 0805; Manufacturer: Vishay-Dale; Power_W: 125mW; TempCo: 200 ppm/C; Value_Code: 100R; Value: 100; EIA_Code: E24; SizeX_mm: 2; SizeY_mm: 1.25; SizeZ_mm: 1.45; Value2: 0.125W; SizeArea_mm2: 2.5; AEC Qualified: Y; VDC_V: 150V; AEC Category: Q200; AEC Grade: 0
R52 = CMP-0025885-5: RES, 0, 5%, 0.1 W, 0603; Manufacturer: Yageo; Power_W: 100mW; TempCo: 200 ppm/C; Value_Code: 0000; Value: 0; EIA_Code: E24; SizeX_mm: 1.6; SizeZ_mm: 1; Value2: 0.1W; SizeArea_mm2: 1.28; AEC Qualified: N; VDC_V: 75V; AEC Category: Q200; SizeY_mm: 0.8; SizeAreaWB_mm2: 4.68
R53 R71 = CMP-0025958-3: RES, 10.0 k, 1%, 0.063 W, AEC-Q200 Grade 0, 0402; Manufacturer: Vishay-Dale; Power_W: 63mW; TempCo: 100 ppm/C; Value_Code: 10k0; Value: 10.0k; EIA_Code: E96; Res_ohm: 10k; SizeX_mm: 1; SizeY_mm: 0.5; SizeZ_mm: 0.6; Value2: 0.063W; AEC Qualified: Y; VDC_V: 50V; AEC Category: Q200; AEC Grade: 0
R54 = CMP-0026859-2: RES, 1.0 M, 5%, 0.063 W, AEC-Q200 Grade 0, 0402; Manufacturer: Vishay-Dale; Value: 1.0Meg; Res_ohm: 1M; Value_Code: 1M00; Power_W: 63mW; Value2: 0.063W; VDC_V: 50V; TempCo: 200 ppm/C; SizeArea_mm2: 0.5; SizeX_mm: 1; SizeZ_mm: 0.6; EIA_Code: E24; AEC Category: Q200; AEC Qualified: Y; AEC Grade: 0
R56 = CMP-0026436-2: RES, 511, 1%, 0.063 W, AEC-Q200 Grade 0, 0402; Manufacturer: Vishay-Dale; Power_W: 63mW; TempCo: 100 ppm/C; Value_Code: 511R; Value: 511; EIA_Code: E96; SizeX_mm: 1; SizeY_mm: 0.5; SizeZ_mm: 0.6; Value2: 0.063W; AEC Qualified: Y; VDC_V: 50V; AEC Category: Q200; AEC Grade: 0
R58 = CMP-0026162-2: RES, 20.0 k, 1%, 0.063 W, AEC-Q200 Grade 0, 0402; Manufacturer: Vishay-Dale; Power_W: 63mW; TempCo: 100 ppm/C; Value_Code: 20k0; Value: 20.0k; EIA_Code: E96; Res_ohm: 20k; SizeX_mm: 1; SizeY_mm: 0.5; SizeZ_mm: 0.6; Value2: 0.063W; AEC Qualified: Y; VDC_V: 50V; AEC Category: Q200; AEC Grade: 0
R60 = CMP-0027004-2: RES, 0, 5%, 0.063 W, 0402; Manufacturer: Yageo America; Power_W: 63mW; TempCo: 200 ppm/C; Value_Code: 0000; U/M: EA; Value: 0; EIA_Code: E24; SizeX_mm: 1; SizeY_mm: 0.5; SizeZ_mm: 0.6; Value2: 0.063W; VDC_V: 50V; AEC Category: Q200
R64 = CMP-0026027-3: RES, 15.0 k, 1%, 0.063 W, AEC-Q200 Grade 0, 0402; Manufacturer: Vishay-Dale; Power_W: 63mW; TempCo: 100 ppm/C; Value_Code: 15k0; Value: 15.0k; EIA_Code: E96; Res_ohm: 15k; SizeX_mm: 1; SizeY_mm: 0.5; SizeZ_mm: 0.6; Value2: 0.063W; AEC Qualified: Y; VDC_V: 50V; AEC Category: Q200; AEC Grade: 0
R65 = CMP-0077547-1: RES, 115 k, 1%, 0.0625 W, 0402; Manufacturer: Samsung Electro-Mechanics; Power_W: 62.5mW; TempCo: 300 ppm/C; U/M: EA; Value: 115k; EIA_Code: E96; SizeX_mm: 1.0; SizeY_mm: 0.5; SizeZ_mm: 0.6; AEC Qualified: N; VDC_V: 50V; AEC Category: Q200
R66 R73 = CMP-0081856-1: RES, 0, 0%, 0.2 W, AEC-Q200 Grade 0, 0402; Manufacturer: Vishay-Dale; SizeAreaWB_mm2: 3; SizeArea_mm2: 0.5; AEC Qualified: Y; AEC Category: Q200; Value: 0; SizeZ_mm: 0.6; Power_W: 200mW; VDC_V: 50V; Value2: 0.2W; SizeX_mm: 1
R67 = CMP-0023235-5: RES, 680, 1%, 0.1 W, 0603; Manufacturer: Yageo; Power_W: 100mW; TempCo: 100 ppm/C; Value_Code: 680R; Value: 680; SizeX_mm: 1.6; SizeY_mm: 0.8; SizeZ_mm: 1; Value2: 0.1W; SizeArea_mm2: 1.28; AEC Qualified: N; VDC_V: 75V; AEC Category: Q200; SizeAreaWB_mm2: 4.68
R70 = CMP-0026859-2: RES, 1.0 M, 5%, 0.063 W, AEC-Q200 Grade 0, 0402; Manufacturer: Vishay-Dale; Power_W: 63mW; TempCo: 200 ppm/C; Value_Code: 1M00; Value: 1.0Meg; EIA_Code: E24; Res_ohm: 1M; SizeX_mm: 1; SizeY_mm: 0.5; SizeZ_mm: 0.6; Value2: 0.063W; AEC Qualified: Y; VDC_V: 50V; AEC Category: Q200; AEC Grade: 0
R72 = CMP-0023253-5: RES, 6.80 k, 1%, 0.1 W, 0603; Manufacturer: Yageo; Power_W: 100mW; TempCo: 100 ppm/C; Value_Code: 6k80; Value: 6.80k; Res_ohm: 6.8k; SizeX_mm: 1.6; SizeY_mm: 0.8; SizeZ_mm: 1; Value2: 0.1W; SizeArea_mm2: 1.28; AEC Qualified: N; VDC_V: 75V; AEC Category: Q200; SizeAreaWB_mm2: 4.68
R74 = CMP-0078244-2: RES, 30.0 k, 1%, 0.063 W, AEC-Q200 Grade 0, 0402; Manufacturer: Vishay-Dale; Power_W: 63mW; Green_Lifecycle: Active; TempCo: 100 ppm/C; Value_Code: 30k0; Green_REACh: Passed; Value: 30.0k; Res_ohm: 30k; SizeX_mm: 1; SizeY_mm: 0.5; SizeZ_mm: 0.6; Value2: 0.063W; AEC Qualified: Y; VDC_V: 50V; AEC Grade: 0; AEC Category: Q200
R?#10 R?#11 = CMP-0017793-3: RES, 0.68, 1%, 0.25 W, AEC-Q200 Grade 0, 1206; Manufacturer: Panasonic; Power_W: 250mW; TempCo: 250 ppm/C; Value_Code: R680; Value: 0.68; EIA_Code: E96; SizeX_mm: 3.2; SizeY_mm: 1.6; SizeZ_mm: 1.35; Value2: 0.25W; SizeArea_mm2: 5.12; AEC Qualified: Y; AEC Category: Q200; AEC Grade: 0; SizeAreaWB_mm2: 10.92
R?#12 = CMP-0022957-5: RES, 26.1 k, 1%, 0.1 W, 0603; Manufacturer: Yageo; Power_W: 100mW; TempCo: 100 ppm/C; Value_Code: 26k1; Value: 26.1k; EIA_Code: E96; SizeX_mm: 1.6; SizeY_mm: 0.8; SizeZ_mm: 1; Value2: 0.1W; SizeArea_mm2: 1.28; AEC Qualified: N; VDC_V: 75V; AEC Category: Q200; SizeAreaWB_mm2: 4.68
R?#13 = CMP-0026742-1: RES, 6.80 k, 1%, 0.0625 W, 0402; Manufacturer: Yageo America; Power_W: 62.5mW; TempCo: 100 ppm/C; Value_Code: 6k80; U/M: EA; Value: 6.80k; Res_ohm: 6.8k; SizeX_mm: 1; SizeY_mm: 0.5; SizeZ_mm: 0.6; AEC Qualified: N; VDC_V: 50V; AEC Category: Q200
R?#14 = CMP-0026539-2: RES, 73.2 k, 1%, 0.063 W, AEC-Q200 Grade 0, 0402; Manufacturer: Vishay-Dale; Power_W: 63mW; TempCo: 100 ppm/C; Value_Code: 73k2; Value: 73.2k; EIA_Code: E96; SizeX_mm: 1; SizeY_mm: 0.5; SizeZ_mm: 0.6; Value2: 0.063W; AEC Qualified: Y; VDC_V: 50V; AEC Category: Q200; AEC Grade: 0
R?#15 = CMP-0026076-3: RES, 1.13 k, 1%, 0.063 W, AEC-Q200 Grade 0, 0402; Manufacturer: Vishay-Dale; Power_W: 63mW; TempCo: 100 ppm/C; Value_Code: 1k13; Value: 1.13k; EIA_Code: E96; SizeX_mm: 1; SizeY_mm: 0.5; SizeZ_mm: 0.6; Value2: 0.063W; AEC Qualified: Y; VDC_V: 50V; AEC Category: Q200; AEC Grade: 0
R?#16 = CMP-0026445-2: RES, 53.6 k, 1%, 0.063 W, AEC-Q200 Grade 0, 0402; Manufacturer: Vishay-Dale; Power_W: 63mW; TempCo: 100 ppm/C; Value_Code: 53k6; Value: 53.6k; EIA_Code: E96; SizeX_mm: 1; SizeY_mm: 0.5; SizeZ_mm: 0.6; Value2: 0.063W; AEC Qualified: Y; VDC_V: 50V; AEC Category: Q200; AEC Grade: 0
R?#17 = CMP-0026435-2: RES, 511 k, 1%, 0.063 W, AEC-Q200 Grade 0, 0402; Manufacturer: Vishay-Dale; Power_W: 63mW; TempCo: 100 ppm/C; Value: 511k; EIA_Code: E96; SizeX_mm: 1; SizeY_mm: 0.5; SizeZ_mm: 0.6; Value2: 0.063W; AEC Qualified: Y; VDC_V: 50V; AEC Category: Q200; AEC Grade: 0
R?#18 = CMP-0025988-3: RES, 127 k, 1%, 0.063 W, AEC-Q200 Grade 0, 0402; Manufacturer: Vishay-Dale; Power_W: 63mW; TempCo: 100 ppm/C; Value: 127k; EIA_Code: E96; SizeX_mm: 1; SizeY_mm: 0.5; SizeZ_mm: 0.6; Value2: 0.063W; AEC Qualified: Y; VDC_V: 50V; AEC Category: Q200; AEC Grade: 0
RT2 = CMP-0002523-3: Thermistor NTC, 47k ohm, 5%, 0603; Manufacturer: MuRata; TaMax_C: 125°C; SizeX_mm: 1.6; SizeY_mm: 0.8; TaMin_C: -40°C; Power_W: 100mW; SizeZ_mm: 1; SizeArea_mm2: 1.28; SizeAreaWB_mm2: 4.68; U/M: EA
T3 = CMP-0087465-1: Lm=200uH, Llk=5uH / P:S1:S2:A = 40:10:10:15; Manufacturer: Renco Electronics; AEC Qualified: No; SizeZ_mm: 0.66inch; DCR_ohm: 0.1; Ind_H: 110µH; Ns1toNp: 2.5:0.5:1:0.5:1
U8 = CMP-0084866-4: 2.9-V to 18-V, 3-A Synchronous Buck Converters, RPJ0009A (VQFN-HR-9); Alternate PartNumber: TPS62903RPJT; Alternate Manufacturer: Texas Instruments; SizeArea_mm2: 3; AEC Category: Q200; SizeX_mm: 1.5; SizeY_mm: 2; SizeAreaWB_mm2: 7.5; SizeZ_mm: 1; CompType: IC; AEC Qualified: N
U9 = CMP-0860377-2: 4-A/6-A, Single-Channel Reinforced Isolation Gate Driver with High Noise Immunity, DWV0008A (SOIC-8); Manufacturer: Texas Instruments; SizeX_mm: 11.5; SizeArea_mm2: 67.275; SizeAreaWB_mm2: 105.975; CompType: IC; SizeZ_mm: 2.8; SizeY_mm: 5.85; AEC Category: Q200; AEC Qualified: N
U10 = CMP-0086087-1: UCC28781RTW, RTW0024B (WQFN-24); Manufacturer: Texas Instruments; SizeY_mm: 4; SizeZ_mm: 0.8; AEC Category: Q200; SizeArea_mm2: 16; CompType: IC; AEC Qualified: N; SizeAreaWB_mm2: 25
U11 = CMP-0087394-2: Optoisolator Transistor Output 5000Vrms 1 Channel 6-SO; Manufacturer: Toshiba; CTR (Max): 300%; CTR (Min): 100%; SizeZ_mm: 2.3mm
U12 = CMP-0066199-1: 2.5V Low Iq Adjustable Precision Shunt Regulator, DBZ0003A (SOT-23-3); Manufacturer: Texas Instruments; SizeArea_mm2: 7.5; SizeAreaWB_mm2: 14.0; SizeX_mm: 2.5; SizeY_mm: 3.0; SizeZ_mm: 1.12; CompType: IC; U/M: EA

## Sheet BatteryBackupSystemAUX.SchDoc
size 431 x 279 mm; Date: Not shown in title block; ApprovedBy: Not shown in title block; CheckedBy: Not shown in title block; Author: Not shown in title block; CompanyName: Not shown in title block; Engineer: Not shown in title block; Organization: Not shown in title block; Address1: Not shown in title block; Address2: Not shown in title block; Address3: Not shown in title block; Address4: Not shown in title block; DocumentNumber: 1; Revision: Use project parameter SCH_Rev; SheetNumber: 3; SheetTotal: 4; PageSetup: Record=PageOptions¦CenterHorizontal=True¦CenterVertical=True¦PrintScale=1.00¦XCorrection=1.00¦YCorrection=1.00¦PrintKind=0¦BorderSize=5000000¦LeftOffset=0¦BottomOffset=0¦Orientation=2¦PaperLength=1000¦PaperWidth=1000¦Scale=100¦PaperSource=15¦PrintQuality=600¦MediaType=1¦DitherType=10¦PaperKind=Letter¦PrintScaleMode=1
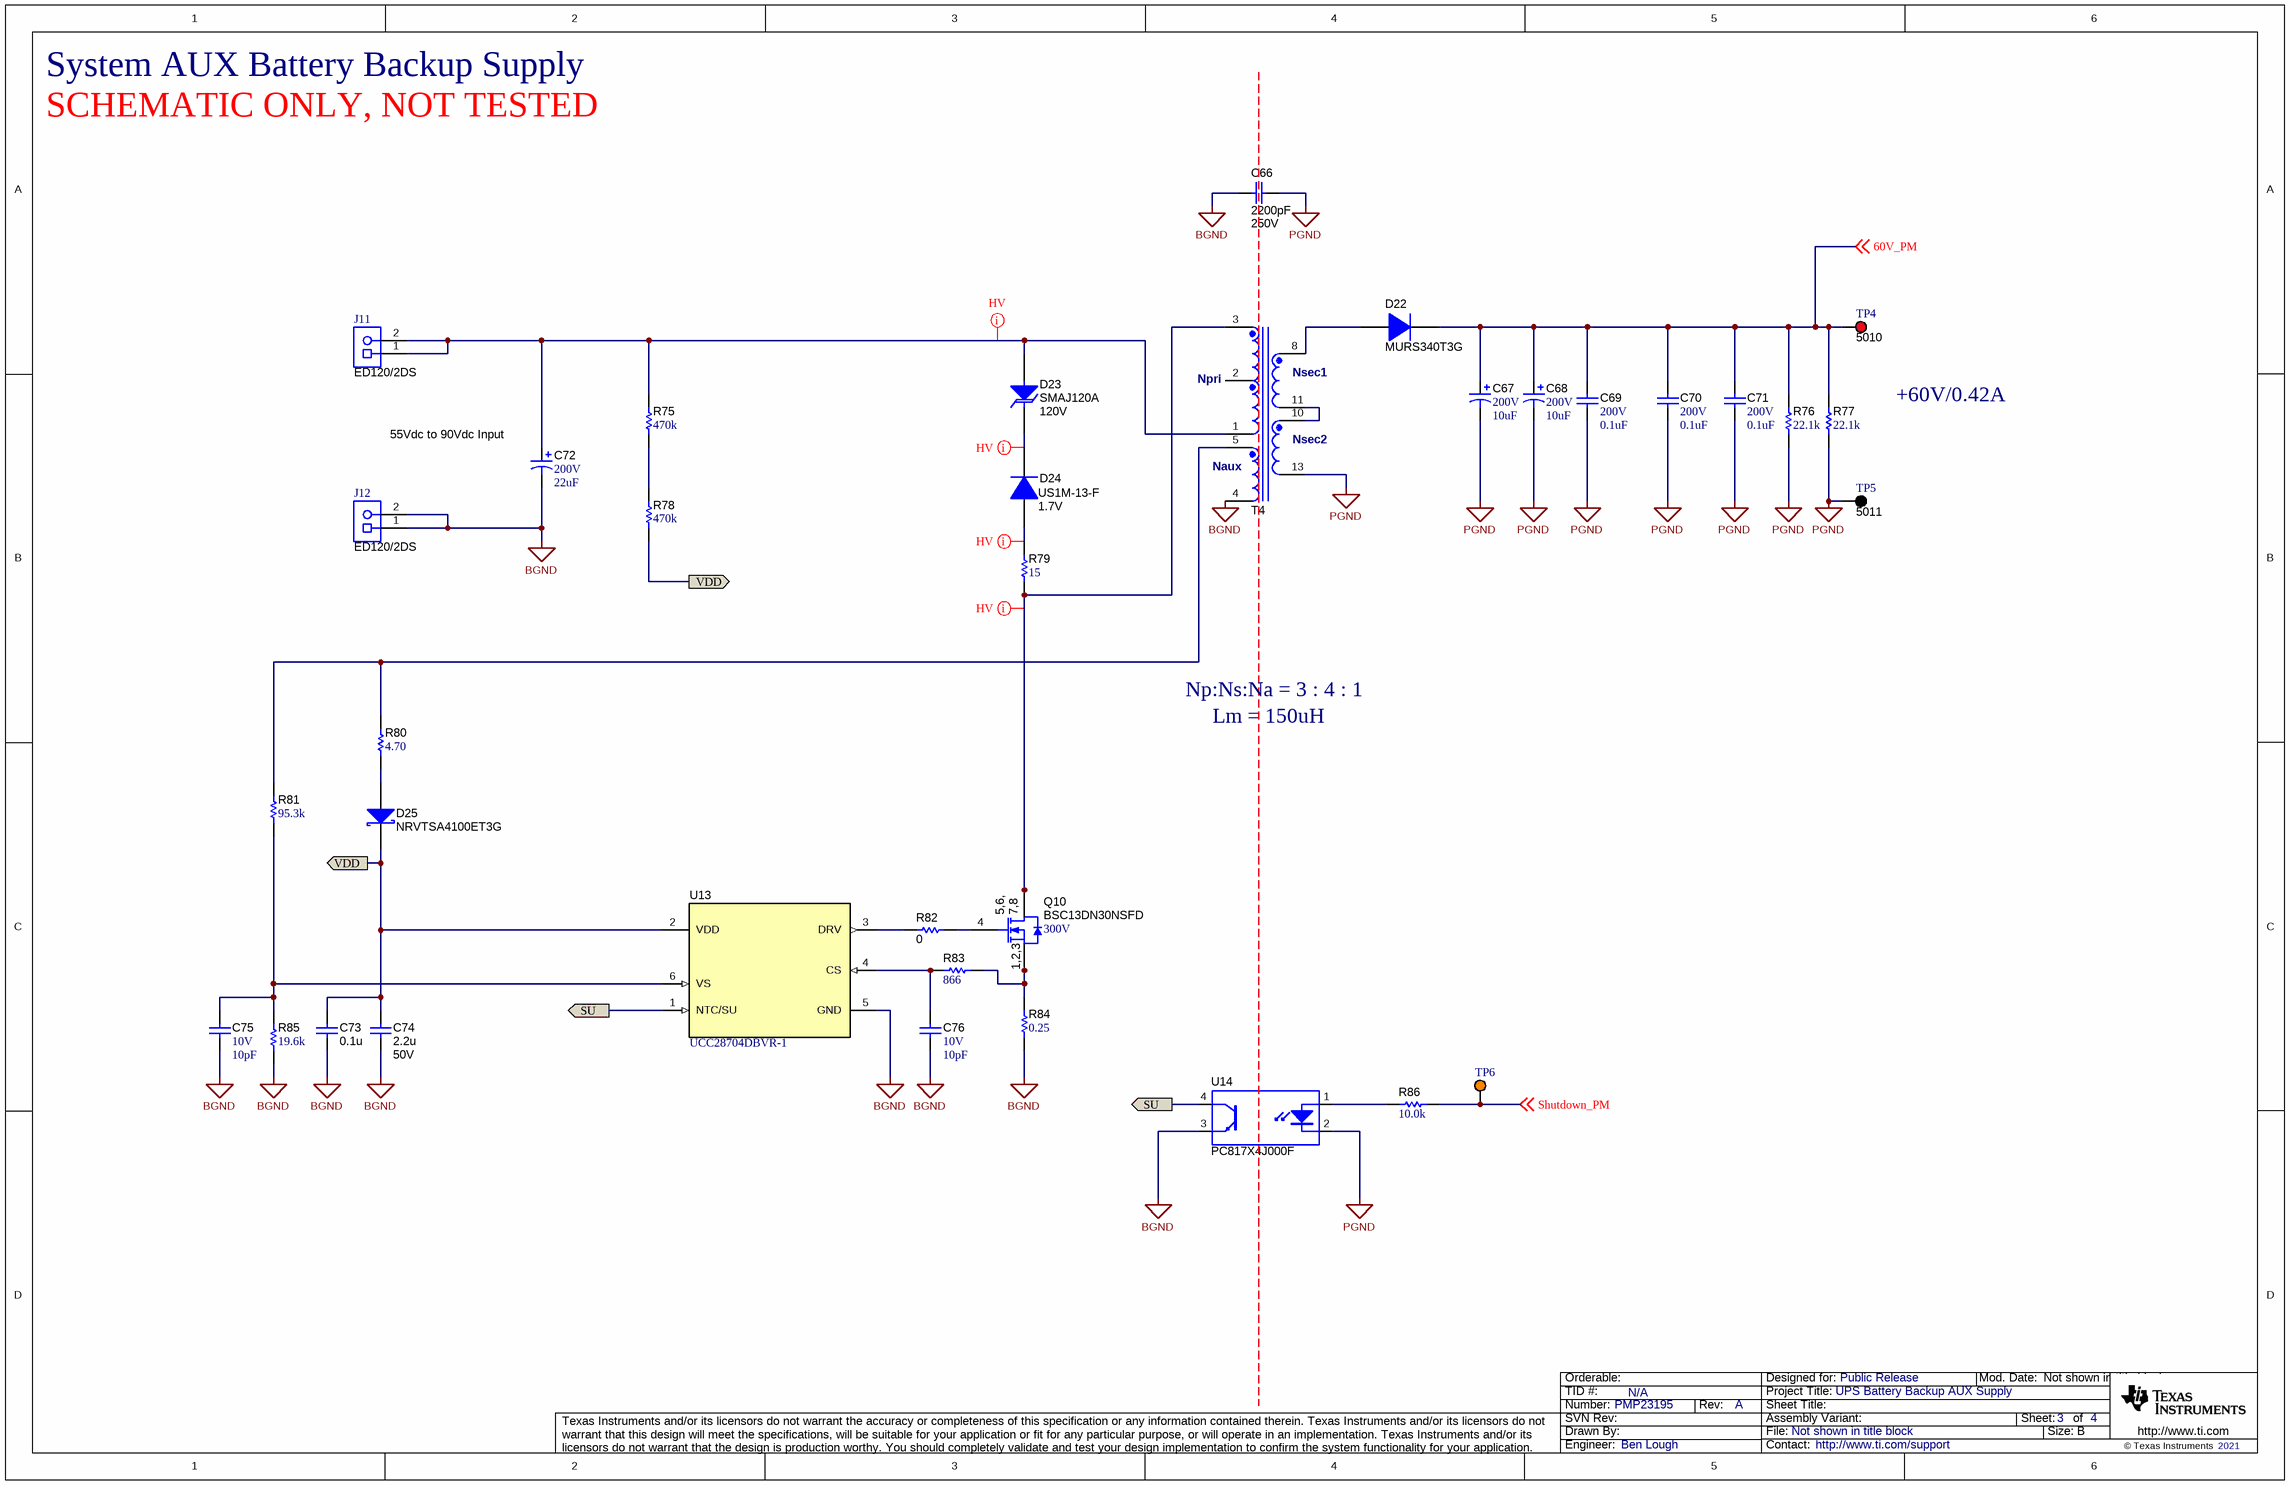
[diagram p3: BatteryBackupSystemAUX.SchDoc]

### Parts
C66  ValueDisplayed: 2200pF  Value2: 250V  [CAPRD750W60D1050H1450]  (hidden comment: CS11-E2GA222MYNS)
C67  VDC_V: 200V  ValueDisplayed: 10uF  [VK_800X1150]  (hidden comment: UVK2D100MPD)
C68  VDC_V: 200V  ValueDisplayed: 10uF  [VK_800X1150]  (hidden comment: UVK2D100MPD)
C69  VDC_V: 200V  ValueDisplayed: 0.1uF  [1206]  (hidden comment: C1206C104K2RACTU)
C70  VDC_V: 200V  ValueDisplayed: 0.1uF  [1206]  (hidden comment: C1206C104K2RACTU)
C71  VDC_V: 200V  ValueDisplayed: 0.1uF  [1206]  (hidden comment: C1206C104K2RACTU)
C72  VDC_V: 200V  ValueDisplayed: 22uF  [UPW_1000x2000]  (hidden comment: UPW2D220MPD1TD)
C73  ValueDisplayed: 0.1u  [0603]  (hidden comment: 06035C104KAT2A)
C74  ValueDisplayed: 2.2u  Value2: 50V  [1206]  (hidden comment: GRM31CR61H225KA88L)
C75  VDC_V: 10V  ValueDisplayed: 10pF  [0402]  (hidden comment: C0402C100C8GACTU)
C76  VDC_V: 10V  ValueDisplayed: 10pF  [0402]  (hidden comment: C0402C100C8GACTU)
D22  MURS340T3G  [SMC]
D23  SMAJ120A  value 120V  [SMA]
D24  US1M-13-F  value 1.7V  [SMA]
D25  NRVTSA4100ET3G  [SMA]
J11  ED120/2DS  [On-Shore_ED120_2DS]
J12  ED120/2DS  [On-Shore_ED120_2DS]
Q10  BSC13DN30NSFD  value 300V  [PG-TDSON-8]
R75  ValueDisplayed: 470k  [1206]  (hidden comment: RC1206FR-07470KL)
R76  ValueDisplayed: 22.1k  [1206]  (hidden comment: RC1206FR-0722K1L)
R77  ValueDisplayed: 22.1k  [1206]  (hidden comment: RC1206FR-0722K1L)
R78  ValueDisplayed: 470k  [1206]  (hidden comment: RC1206FR-07470KL)
R79  ValueDisplayed: 15  [1206]  (hidden comment: CRCW120615R0JNEA)
R80  ValueDisplayed: 4.70  [1206]  (hidden comment: RC1206FR-074R7L)
R81  ValueDisplayed: 95.3k  [0603]  (hidden comment: RC0603FR-0795K3L)
R82  value 0  [0603]  (hidden comment: CRCW06030000Z0EA)
R83  ValueDisplayed: 866  [0603]  (hidden comment: RC0603FR-07866RL)
R84  ValueDisplayed: 0.25  [1206]  (hidden comment: CSR1206FKR250)
R85  ValueDisplayed: 19.6k  [0603]  (hidden comment: RC0603FR-0719K6L)
R86  ValueDisplayed: 10.0k  [0603]  (hidden comment: M55342K12B10E0T)
T4  750314727  [WURTH_750314727]  (value not drawn)
TP4  5010  [Keystone5010]
TP5  5011  [Keystone5011]
TP6  5013  [Keystone5013]  (value not drawn)
U13  UCC28704DBVR-1  [DBV0006A_N]
U14  PC817X4J000F  [DIP762W60P254L460H350Q4B]

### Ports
SU (out), VDD (out)

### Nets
BGND: C66.2 C72.2(-) C73.2 C74.2 C75.2 C76.2 J12.1 J12.2 R84.1 R85.1 T4.4 U13.5(GND) U14.3(E)
PGND: C66.1 C67.2(-) C68.2(-) C69.2 C70.2 C71.2 R76.1 R77.1 T4.13 TP5.1 U14.2(K)
60V_PM: C67.1(+) C68.1(+) C69.1 C70.1 C71.1 D22.1(K) R76.2 R77.2 TP4.1 ; off-sheet 60V_PM
Shutdown_PM: R86.2 TP6.1 ; off-sheet Shutdown_PM
SU: U13.1(NTC/SU) U14.4(C) ; port SU
VDD: C73.1 C74.1 D25.1(K) R78.1 U13.2(VDD) ; port VDD
NetC72_1: C72.1(+) D23.2(A) J11.1 J11.2 R75.2 T4.1
NetC75_1: C75.1 R81.1 R85.2 U13.6(VS)
NetC76_1: C76.1 R83.1 U13.4(CS)
NetD22_2: D22.2(A) T4.8
NetD23_1: D23.1(K) D24.1(K)
NetD24_2: D24.2(A) R79.2
NetD25_2: D25.2(A) R80.1
NetQ10_1: Q10.1(S) Q10.2(S) Q10.3(S) R83.2 R84.2
NetQ10_4: Q10.4(G) R82.2
NetQ10_5: Q10.5(D) Q10.6(D) Q10.7(D) Q10.8(D) Q10.9(D) R79.1 T4.3
NetR75_1: R75.1 R78.2
NetR80_2: R80.2 R81.2 T4.5
NetR82_1: R82.1 U13.3(DRV)
NetR86_1: R86.1 U14.1(A)
NetT4_10: T4.10 T4.11

Not connected (* = marked no-connect by the designer): T4 2

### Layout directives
net class HV: NetC72_1, NetD23_1, NetD24_2, NetQ10_5

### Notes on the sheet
- System AUX Battery Backup Supply
- SCHEMATIC ONLY, NOT TESTED
- (near C72) 55Vdc to 90Vdc Input
- (near T4) Npri
- (near T4) Nsec1
- +60V/0.42A
- (near T4) Naux
- (near T4) Nsec2
- Np:Ns:Na = 3 : 4 : 1
- Lm = 150uH

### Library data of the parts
C66 = CS11-E2GA222MYNS: CAP, CERM, 2200pF, 250V, +/-20%, E, Radial Disc D10.5x7mm; Manufacturer: TDK; Polarized: N; CompType: Capacitor; U/M: EA; Cap_F: 0.0000000022; Tolerance_%: 20; Value1: Unknown; VDC_V: 250; TaMin_C: -25; TaMax_C: 105; Cap_Case: Disc, 10.5x7mm
C67 C68 = CMP-0064891-1: CAP, AL, 10 uF, 200 V, +/- 20%, TH; Manufacturer: Nichicon; TaMin_C: -40°C; Polarized: Y; SizeAreaWB_mm2: 100; Value1: Unknown; U/M: EA; Value: 10uF; TaMax_C: 85°C; SizeZ_mm: 13; SizeX_mm: 8; Cap_Case: 8x11.5mm; SizeArea_mm2: 64; CompType: Capacitor; AEC Qualified: N; Cap_F: 10µF; IRMS_A: 80mA; AEC Category: Q200
C69-C71 = CMP-0008585-2: CAP, CERM, 0.1 uF, 200 V, +/- 10%, X7R, 1206; Manufacturer: Kemet; TaMin_C: -55°C; Polarized: N; SizeAreaWB_mm2: 10.92; Value1: Unknown; U/M: EA; Value: 0.1uF; TaMax_C: 125°C; SizeZ_mm: 1.35; SizeX_mm: 3.2; SizeY_mm: 1.6; SizeArea_mm2: 5.12; Cap_F: 100nF; AEC Category: Q200
C72 = CMP-0064890-1: CAP, AL, 22 uF, 200 V, +/- 20%, TH; Manufacturer: Nichicon; TaMin_C: -40°C; Polarized: Y; SizeAreaWB_mm2: 144; Value1: Unknown; U/M: EA; Value: 22uF; TaMax_C: 105°C; SizeZ_mm: 22; SizeX_mm: 10; Cap_Case: 10x20mm; SizeArea_mm2: 100; CompType: Capacitor; AEC Qualified: N; Cap_F: 22µF; IRMS_A: 1.4dA; AEC Category: Q200
C73 = 06035C104KAT2A: CAP, CERM, 0.1uF, 50V, +/-10%, X7R, 0603; Manufacturer: AVX; Polarized: N; CompType: Capacitor; U/M: EA; Cap_F: 0.0000001; Tolerance_%: 10; Value1: Unknown; VDC_V: 50; TaMin_C: -55; TaMax_C: 125
C74 = GRM31CR61H225KA88L: CAP, CERM, 2.2uF, 50V, +/-10%, X5R, 1206; Manufacturer: MuRata; Polarized: N; CompType: Capacitor; U/M: EA; Cap_F: 0.0000022; Tolerance_%: 10; Value1: Unknown; VDC_V: 50; TaMin_C: -55; TaMax_C: 85
C75 C76 = CMP-0064914-2: CAP, CERM, 10 pF, 10 V,+/- 2.5%, C0G/NP0, 0402; Manufacturer: Kemet; TaMin_C: -55°C; Polarized: N; SizeAreaWB_mm2: 3; Value1: Unknown; U/M: EA; Value: 10pF; TaMax_C: 125°C; SizeZ_mm: 0.6; SizeX_mm: 1; SizeY_mm: 0.5; AEC Category: Q200
D22 = CMP-0076962-2: Diode, Ultrafast, 400 V, 3 A, SMC; Manufacturer: ON Semiconductor; AEC Category: Q101; Io_A: 3A; RJC_CperW: 11.0; SizeArea_mm2: 50.5686; SizeX_mm: 8.13; SizeZ_mm: 2.6; SizeAreaWB_mm2: 83.2686; TJmax_C: 175°C; Green_REACh: Incomplete; Value2: 1.25V; Vr_V: 400V; Green_Lifecycle: Not Set; SizeY_mm: 6.22; Value: 400V
D23 = SMAJ120A: Diode, TVS, Uni, 120V, 400W, SMA; Manufacturer: Littelfuse; U/M: EA; Power_W: 400; Vr_V: 120
D24 = US1M-13-F: Diode, Ultrafast, 1000V, 1A, SMA; Manufacturer: Diodes Inc.; U/M: EA; Vf_V: 1.7; Io_A: 1; Vr_V: 1000; TJmax_C: 150; RJC_CperW: 30
D25 = CMP-0081057-2: Diode, Schottky, 100 V, 4 A, AEC-Q101, SMA; Manufacturer: ON Semiconductor; SizeZ_mm: 2.87; SizeY_mm: 2.92; SizeAreaWB_mm2: 37.3428; Io_A: 4A; AEC Category: Q101; SizeX_mm: 5.59; Value: 100V; SizeArea_mm2: 16.3228; Value2: 0.68V; TJmax_C: 175°C; AEC Qualified: Y; Vf_V: 680mV
J11 J12 = CMP-0074910-1: Terminal Block, 5.08 mm, 2x1, Brass, TH; Manufacturer: On-Shore Technology; Cert_VDE: Y; CNHeader: False; Current_A: 15A; Green_Lifecycle: Not Set; Shrouded: N; Gender: Female; Green_REACh: Incomplete; Voltage_V: 300V; Row_Count: 1; Pitch_mm: 5.08; CT: True
Q10 = CMP-0000907-1: MOSFET, N-CH, 300 V, 16 A, PG-TDSON-8; Alternate Manufacturer: None; Manufacturer: Infineon Technologies; SizeZ_mm: 1.12; ChType: N; SizeX_mm: 5.99; SizeY_mm: 4.9; Vgs_V: 20V; SizeArea_mm2: 29.351; IdsMax_A: 16A; SizeAreaWB_mm2: 55.131; U/M: EA; QgTyp_nC: 23
R75 R78 = CMP-0018313-2: RES, 470 k, 1%, 0.25 W, 1206; Manufacturer: Yageo America; Power_W: 250mW; TempCo: 100 ppm/C; U/M: EA; Value: 470k; SizeX_mm: 3.2; SizeY_mm: 1.6; SizeZ_mm: 1.35; Value2: 0.25W; SizeArea_mm2: 5.12; VDC_V: 200V; AEC Category: Q200
R76 R77 = CMP-0018082-2: RES, 22.1 k, 1%, 0.25 W, 1206; Manufacturer: Yageo America; Power_W: 250mW; TempCo: 100 ppm/C; Value_Code: 22k1; U/M: EA; Value: 22.1k; EIA_Code: E96; SizeX_mm: 3.2; SizeY_mm: 1.6; SizeZ_mm: 1.35; Value2: 0.25W; SizeArea_mm2: 5.12; VDC_V: 200V; AEC Category: Q200
R79 = CMP-0018594-3: RES, 15, 5%, 0.25 W, AEC-Q200 Grade 0, 1206; Manufacturer: Vishay-Dale; Power_W: 250mW; TempCo: 200 ppm/C; Value_Code: 15R0; Value: 15; EIA_Code: E24; SizeX_mm: 3.2; SizeY_mm: 1.6; SizeZ_mm: 1.35; Value2: 0.25W; SizeArea_mm2: 5.12; AEC Qualified: Y; VDC_V: 200V; AEC Category: Q200; AEC Grade: 0
R80 = CMP-0018350-2: RES, 4.70, 1%, 0.25 W, 1206; Manufacturer: Yageo America; Power_W: 250mW; TempCo: 200 ppm/C; Value_Code: 4R70; U/M: EA; Value: 4.70; Res_ohm: 4.7; SizeX_mm: 3.2; SizeY_mm: 1.6; SizeZ_mm: 1.35; Value2: 0.25W; SizeArea_mm2: 5.12; VDC_V: 200V; AEC Category: Q200
R81 = CMP-0023326-5: RES, 95.3 k, 1%, 0.1 W, 0603; Manufacturer: Yageo; Power_W: 100mW; TempCo: 100 ppm/C; Value_Code: 95k3; Value: 95.3k; EIA_Code: E96; SizeX_mm: 1.6; SizeY_mm: 0.8; SizeZ_mm: 1; Value2: 0.1W; SizeArea_mm2: 1.28; AEC Qualified: N; VDC_V: 75V; AEC Category: Q200; SizeAreaWB_mm2: 4.68
R82 = CRCW06030000Z0EA: RES, 0 ohm, 5%, 0.1W, 0603; Manufacturer: Vishay-Dale; CompType: Resistor; Value_Code: 0000; Tolerance_%: 5; Power_W: 0.1; VDC_V: 75; TempCo: 200 ppm/C; EIA_Code: E24; U/M: EA
R83 = CMP-0023300-5: RES, 866, 1%, 0.1 W, 0603; Manufacturer: Yageo; Power_W: 100mW; TempCo: 100 ppm/C; Value_Code: 866R; Value: 866; EIA_Code: E96; SizeX_mm: 1.6; SizeY_mm: 0.8; SizeZ_mm: 1; Value2: 0.1W; SizeArea_mm2: 1.28; AEC Qualified: N; VDC_V: 75V; AEC Category: Q200; SizeAreaWB_mm2: 4.68
R84 = CMP-0017267-2: RES, 0.25, 1%, 0.5 W, 1206; Manufacturer: Stackpole Electronics Inc; Power_W: 500mW; TempCo: 100 ppm/C; Value_Code: R250; U/M: EA; Value: 0.25; Res_ohm: 2.5d; SizeX_mm: 3.2; SizeY_mm: 1.6; SizeZ_mm: 1.35; Value2: 0.5W; SizeArea_mm2: 5.12; AEC Category: Q200
R85 = CMP-0022861-5: RES, 19.6 k, 1%, 0.1 W, 0603; Manufacturer: Yageo; Power_W: 100mW; TempCo: 100 ppm/C; Value_Code: 19k6; Value: 19.6k; EIA_Code: E96; SizeX_mm: 1.6; SizeY_mm: 0.8; SizeZ_mm: 1; Value2: 0.1W; SizeArea_mm2: 1.28; AEC Qualified: N; VDC_V: 75V; AEC Category: Q200; SizeAreaWB_mm2: 4.68
R86 = CMP-0080488-1: RES, 10.0 k, 1%, 0.1 W, 0603; Manufacturer: TT Electronics/IRC; Power_W: 100mW; TempCo: 100 ppm/C; SizeAreaWB_mm2: 4.68; Value_Code: 10k0; Value: 10.0k; EIA_Code: E96; Res_ohm: 10k; SizeX_mm: 1.6; SizeY_mm: 0.8; SizeZ_mm: 1; Value2: 0.1W; SizeArea_mm2: 1.28; AEC Qualified: N; AEC Category: Q200
T4 = 750314727: Transformer, 80uH, TH; Manufacturer: Wurth Elektronik eiSos; SymbolCreator: x0208325; DCR_Ohm: 0.221; Value: 250uH; LeakageL: TBD; U/M: EA
TP4 = CMP-0055147-2: Test Point, Multipurpose, Red, TH; Manufacturer: Keystone Electronics; CT: TRUE; ContactFinish: Silver; Green_Lifecycle: Active; CNHeader: FALSE; Green_REACh: Passed
TP5 = CMP-0055148-2: Test Point, Multipurpose, Black, TH; Manufacturer: Keystone Electronics; CNHeader: FALSE; ContactFinish: Silver; Green_REACh: Passed; Green_Lifecycle: Active; CT: TRUE
TP6 = CMP-0055150-2: Test Point, Multipurpose, Orange, TH; Manufacturer: Keystone Electronics; CT: TRUE; ContactFinish: Silver; Green_REACh: Passed; CNHeader: FALSE; Green_Lifecycle: Active
U13 = CMP-0074087-1: Off-Line Constant-Voltage Constant-Current Flyback Controller With Primary-Side Regulation (PSR), DBV0006A (SOT-23-6); Alternate PartNumber: UCC28704DBVT-1; Alternate Manufacturer: Texas Instruments; Green_Lifecycle: Active; SizeAreaWB_mm2: 14.82; Green_REACh: Passed; U/M: EA; SizeZ_mm: 1.45; SizeX_mm: 2.8; SizeY_mm: 2.9; SizeArea_mm2: 8.12; CompType: IC
U14 = LTV-817: Opto-Isolator, 1 Channel, TH; CompType: OPTOCOUPLER; U/M: EA

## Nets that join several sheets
BGND: BatteryBackupPowerModule (13 pins), BatteryBackupSystemAUX (13 pins)
GND2: PowerModule_ZVS_Flyback (C12.2 C22.2 U6.4), SystemAUX_ZVSFlyback (C38.2 U11.4)
GND_P: PowerModule_ZVS_Flyback (C28.2 U4.4), SystemAUX_ZVSFlyback (C56.2 U9.4)
GND_S: PowerModule_ZVS_Flyback (13 pins), SystemAUX_ZVSFlyback (19 pins)
PGND: BatteryBackupPowerModule (11 pins), PowerModule_ZVS_Flyback (27 pins), SystemAUX_ZVSFlyback (28 pins), BatteryBackupSystemAUX (11 pins)
60V_PM: BatteryBackupPowerModule (9 pins), BatteryBackupSystemAUX (9 pins)
80V: PowerModule_ZVS_Flyback (D6.2), SystemAUX_ZVSFlyback (D17.2)
Shutdown_PM: BatteryBackupPowerModule (R12.2 TP3.1), BatteryBackupSystemAUX (R86.2 TP6.1)
SU: BatteryBackupPowerModule (U1.1 U2.4), BatteryBackupSystemAUX (U13.1 U14.4)
VDD: BatteryBackupPowerModule (5 pins), BatteryBackupSystemAUX (5 pins)

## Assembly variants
001: not fitted C8 C11 C14 C32 C60 C75 C76 R18 R34 R37 R67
